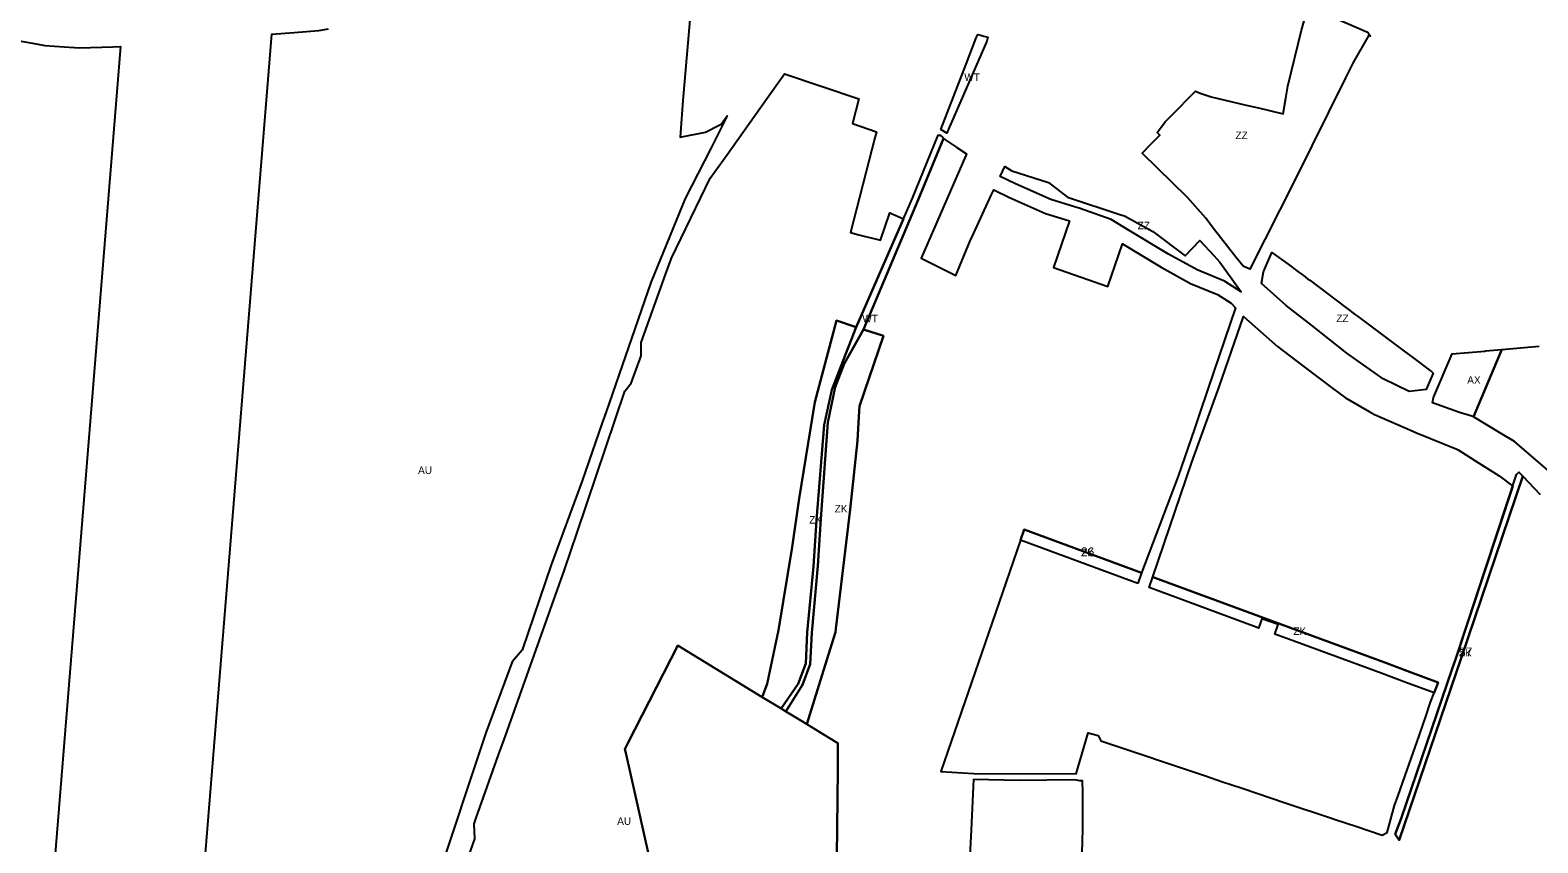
# Model space of a CAD drawing. Extents: x -545779 to -541342, y -1153413 to -1149956.
# Drawn here: x -544840 to -543834, y -1152010 to -1151467 of the extents above; entities that cross this region are included whole.
import ezdxf

# ---------------------------------------------------------------- set-up
doc = ezdxf.new("R2010")
doc.units = 0
for name, color, linetype in [('90640013', 7, 'Continuous'), ('90670013', 7, 'Continuous'), ('90710013', 7, 'Continuous'), ('90710023', 7, 'Continuous'), ('90730023', 7, 'Continuous'), ('90750013', 7, 'Continuous'), ('90760013', 7, 'Continuous'), ('90910012', 7, 'Continuous'), ('ID_navrh', 7, 'Continuous')]:
    doc.layers.add(name, color=color, linetype=linetype)

msp = doc.modelspace()

# ---------------------------------------------------------------- linework, layer by layer
at = {"layer": '90640013'}
for points in [[(-544232.03, -1151533.8), (-544215.08, -1151490.07), (-544208.32, -1151472.48), (-544207.36, -1151470.4), (-544204.65, -1151471.1), (-544203.29, -1151471.45), (-544200.59, -1151472.14), (-544201.35, -1151474.81), (-544226.79, -1151533.59), (-544228.04, -1151536.23)], [(-544338.6, -1151920.06), (-544327.25, -1151903.59), (-544322.08, -1151889.98), (-544321.13, -1151869.42), (-544316.9, -1151825.34), (-544314.86, -1151794.47), (-544309.78, -1151730.92), (-544304.78, -1151707.55), (-544298.72, -1151691.91), (-544288.37, -1151665.55), (-544256.81, -1151593.28), (-544250.8, -1151579.54), (-544233.62, -1151537.42), (-544232.47, -1151537.6), (-544230.64, -1151539.08), (-544230.06, -1151539.72), (-544247.16, -1151580.61), (-544283.6, -1151667.09), (-544296.39, -1151690.01), (-544302.4, -1151705.73), (-544307.28, -1151729.26), (-544312.02, -1151793.5), (-544313.95, -1151824.81), (-544318.14, -1151869.59), (-544319.12, -1151890.49), (-544324.34, -1151904.33), (-544335.32, -1151922.05)]]:
    msp.add_lwpolyline(points, close=True, dxfattribs=at)
at = {"layer": '90670013'}
msp.add_lwpolyline([(-543982.6, -1151453.35), (-543947.72, -1151468.6), (-543946.8, -1151469.22), (-543945.23, -1151471.42), (-543946.34, -1151470.89), (-543956.79, -1151488.97), (-543961.96, -1151499.28), (-543995.62, -1151567.47), (-544025.68, -1151626.95), (-544030.21, -1151624.9), (-544035.12, -1151618.93), (-544050.91, -1151598.59), (-544055.2, -1151593.01), (-544067.38, -1151579.03), (-544097.69, -1151549.46), (-544091.86, -1151543.49), (-544085.85, -1151537.43), (-544087.53, -1151535.79), (-544085.47, -1151532.93), (-544082.3, -1151528.55), (-544078.49, -1151524.76), (-544062.12, -1151508.24), (-544058.828, -1151509.401), (-544054.195, -1151511.034), (-544051.57, -1151511.96), (-544028.31, -1151517.41), (-544020.04, -1151519.34), (-544003.49, -1151523.2), (-544001.76, -1151512.89), (-544000.5, -1151504.81), (-543991.36, -1151467.47), (-543989.48, -1151461.15)], dxfattribs=at)
for points in [[(-544118.3, -1151593.88), (-544139.74, -1151586.23), (-544142.74, -1151585.3), (-544158.48, -1151580.44), (-544182.04, -1151569.98), (-544192.36, -1151565.06), (-544189.294, -1151558.541), (-544184.53, -1151561.26), (-544160.19, -1151569.12), (-544147.45, -1151578.92), (-544111.73, -1151590.65), (-544109.43, -1151591.41), (-544090.42, -1151601.91), (-544068.93, -1151618.03), (-544059.11, -1151607.82), (-544049.77, -1151617.91), (-544045.76, -1151622.18), (-544037.81, -1151633.31), (-544031.62, -1151641.99), (-544042.66, -1151635.02), (-544060.91, -1151627.39), (-544080.04, -1151616.83), (-544107.46, -1151600.39)], [(-543961.06, -1151683.01), (-543984.54, -1151664.4), (-544001.52, -1151651.15), (-544018.07, -1151636.61), (-544016.54, -1151628.79), (-544011.13, -1151615.89), (-544000.16, -1151623.63), (-543993.65, -1151628.41), (-543989.98, -1151631.22), (-543987.19, -1151633.32), (-543985.803, -1151634.36), (-543955.209, -1151657.314), (-543953.858, -1151658.328), (-543923.722, -1151680.938), (-543917.051, -1151685.943), (-543905.289, -1151694.767), (-543904.569, -1151695.308), (-543904.391, -1151695.441), (-543903.789, -1151695.893), (-543903.34, -1151696.23), (-543908.17, -1151707.27), (-543919.38, -1151708.54), (-543936.67, -1151700.16)]]:
    msp.add_lwpolyline(points, close=True, dxfattribs=at)
at = {"layer": '90710013'}
for points in [[(-544326.52, -1151780.05), (-544316.07, -1151715.64), (-544301.51, -1151661.3), (-544288.37, -1151665.55), (-544298.72, -1151691.91), (-544304.78, -1151707.55), (-544309.78, -1151730.92), (-544314.86, -1151794.47), (-544316.9, -1151825.34), (-544321.13, -1151869.42), (-544322.08, -1151889.98), (-544327.25, -1151903.59), (-544338.6, -1151920.06), (-544351.13, -1151912.42), (-544347.9, -1151903.54), (-544340.28, -1151867.89), (-544331.12, -1151812.43)], [(-544325.42, -1151928.09), (-544335.32, -1151922.05), (-544324.34, -1151904.33), (-544319.12, -1151890.49), (-544318.14, -1151869.59), (-544313.95, -1151824.81), (-544312.02, -1151793.5), (-544307.28, -1151729.26), (-544302.4, -1151705.73), (-544296.39, -1151690.01), (-544283.6, -1151667.09), (-544270.24, -1151671.42), (-544286.32, -1151718.42), (-544286.67, -1151725.2), (-544287.51, -1151741.53), (-544292.37, -1151787.39), (-544301.96, -1151866.85), (-544302.25, -1151869.25), (-544309.03, -1151891.14), (-544321.27, -1151930.63)], [(-543921.716, -1151902.65), (-543938.126, -1151896.589), (-543968.413, -1151885.402), (-543996.91, -1151874.876), (-544008.987, -1151870.416), (-544006.81, -1151863.97), (-544017.74, -1151860.181), (-544019.86, -1151866.399), (-544021.489, -1151865.798), (-544093.021, -1151839.376), (-544090.59, -1151832.3), (-544089.09, -1151832.83), (-544019.06, -1151858.7), (-543994.46, -1151867.78), (-543965.95, -1151878.31), (-543935.7, -1151889.49), (-543919.25, -1151895.56), (-543900.09, -1151902.64), (-543902.735, -1151909.661)]]:
    msp.add_lwpolyline(points, close=True, dxfattribs=at)
at = {"layer": '90710023'}
for points in [[(-543924.69, -1151993.54), (-543890.65, -1151893.58), (-543890.642, -1151893.555), (-543888.382, -1151886.723), (-543847.78, -1151763.96), (-543846.21, -1151762.33), (-543843.58, -1151765.07), (-543884.82, -1151886.48), (-543926.06, -1152007.84), (-543928.86, -1152003.9)], [(-544100.474, -1151836.623), (-544178.838, -1151807.679), (-544176.395, -1151800.585), (-544098.053, -1151829.541), (-544098.06, -1151829.56)]]:
    msp.add_lwpolyline(points, close=True, dxfattribs=at)
at = {"layer": '90730023'}
msp.add_lwpolyline([(-544335.32, -1151922.05), (-544325.42, -1151928.09), (-544321.27, -1151930.63), (-544306.99, -1151939.34), (-544300.59, -1151943.25), (-544300.75, -1151957.52), (-544300.79, -1151961.28), (-544302.75, -1152132.72), (-544304.26, -1152265.56), (-544304.43, -1152280.58), (-544367.57, -1152282.1), (-544370.25, -1152270.16), (-544401.66, -1152130.3), (-544421.06, -1152043.91), (-544421.06, -1152043.91), (-544433.09, -1151990.35), (-544442.21, -1151949.72), (-544442.79, -1151947.17), (-544440.77, -1151943.22), (-544407.5, -1151878.02), (-544351.13, -1151912.42), (-544338.6, -1151920.06)], close=True, dxfattribs=at)
at = {"layer": '90750013'}
for points in [[(-544398.431, -1151447.726), (-544404.191, -1151514.379), (-544405.968, -1151538.776), (-544388.93, -1151535.59), (-544379.85, -1151530.83), (-544378.59, -1151530.19), (-544374.44, -1151524.6), (-544385.47, -1151546.37), (-544402.51, -1151579.84), (-544425.47, -1151635.75), (-544455.29, -1151722.05), (-544457.88, -1151729.54), (-544471.2, -1151768.07), (-544492.05, -1151824.34), (-544511.33, -1151881.16), (-544517.9, -1151888.93), (-544535.68, -1151936.25), (-544569.04, -1152036.59)], [(-544863.56, -1151471.74), (-544835.58, -1151476.61), (-544829.76, -1151477.63), (-544817.04, -1151478.48), (-544806.75, -1151479.17), (-544784.41, -1151478.6), (-544779.283, -1151478.465), (-544841.973, -1152250.685)], [(-544742.287, -1152258.607), (-544678.286, -1151470.229), (-544663.43, -1151469.03), (-544646.97, -1151467.7), (-544640.54, -1151466.58)], [(-544549.76, -1152026.71), (-544543.02, -1152007.12), (-544543.4, -1151997.05), (-544541.95, -1151992.96), (-544525.9, -1151947.83), (-544523.61, -1151941.41), (-544496.26, -1151864.52), (-544483.08, -1151827.46), (-544474.71, -1151802.71), (-544474.71, -1151802.71), (-544442.81, -1151708.38), (-544438.68, -1151702.96), (-544432.02, -1151684.69), (-544431.97, -1151675.83), (-544415.57, -1151630.49), (-544411.63, -1151619.63), (-544385.88, -1151566.12), (-544374.27, -1151550.18), (-544348.98, -1151514.49), (-544336.264, -1151496.546), (-544286.643, -1151513.325), (-544290.981, -1151529.804), (-544274.838, -1151535.263), (-544275.88, -1151539.22), (-544292.132, -1151602.506), (-544286.65, -1151603.93), (-544272.13, -1151607.7), (-544265.97, -1151589.28), (-544256.81, -1151593.28), (-544288.37, -1151665.55), (-544301.51, -1151661.3), (-544316.07, -1151715.64), (-544326.52, -1151780.05), (-544331.12, -1151812.43), (-544340.28, -1151867.89), (-544347.9, -1151903.54), (-544351.13, -1151912.42), (-544407.5, -1151878.02), (-544440.77, -1151943.22), (-544442.79, -1151947.17), (-544442.21, -1151949.72), (-544433.09, -1151990.35), (-544421.06, -1152043.91)], [(-544302.75, -1152132.72), (-544300.79, -1151961.28), (-544300.75, -1151957.52), (-544300.59, -1151943.25), (-544306.99, -1151939.34), (-544321.27, -1151930.63), (-544309.03, -1151891.14), (-544302.25, -1151869.25), (-544301.96, -1151866.85), (-544292.37, -1151787.39), (-544287.51, -1151741.53), (-544286.67, -1151725.2), (-544286.32, -1151718.42), (-544270.24, -1151671.42), (-544283.6, -1151667.09), (-544247.16, -1151580.61), (-544230.06, -1151539.72), (-544229.19, -1151540.31), (-544221.23, -1151545.74), (-544214.8, -1151550.04), (-544215.31, -1151551.2), (-544245, -1151619.57), (-544221.98, -1151631.1), (-544212.31, -1151607.99), (-544210.19, -1151603.35), (-544198.06, -1151577.18), (-544196.616, -1151574.109), (-544186.221, -1151579.065), (-544161.996, -1151589.82), (-544145.997, -1151594.76), (-544156.671, -1151625.758), (-544120.556, -1151638.42), (-544110.788, -1151610.054), (-544085.029, -1151625.498), (-544065.268, -1151636.407), (-544047.29, -1151643.923), (-544038.099, -1151649.726), (-544035.294, -1151652.8), (-544049.74, -1151695.3), (-544058.9, -1151722.15), (-544062.77, -1151733.47), (-544073.55, -1151765.03), (-544098.053, -1151829.541), (-544176.395, -1151800.585), (-544178.838, -1151807.679), (-544190.89, -1151842.68), (-544232.03, -1151962.15), (-544209.95, -1151963.48), (-544141.65, -1151963.58), (-544133.597, -1151936.229), (-544126.97, -1151938.18), (-544125.19, -1151941.77), (-544055.43, -1151965.13), (-544044.66, -1151968.73), (-544030.88, -1151973.35), (-544002.09, -1151982.98), (-543971.18, -1151993.33), (-543968.05, -1151994.38), (-543955.12, -1151998.7), (-543937.55, -1152004.59), (-543934.17, -1152002.91), (-543929.23, -1151984.87), (-543926.75, -1151978.09), (-543923.89, -1151969.9), (-543922.08, -1151964.71), (-543912.85, -1151938.25), (-543909.92, -1151929.94), (-543908.53, -1151926), (-543905.1, -1151915.94), (-543902.735, -1151909.661), (-543900.09, -1151902.64), (-543919.25, -1151895.56), (-543935.7, -1151889.49), (-543965.95, -1151878.31), (-543994.46, -1151867.78), (-544019.06, -1151858.7), (-544089.09, -1151832.83), (-544090.59, -1151832.3), (-544064.41, -1151755.76), (-544046.26, -1151705.45), (-544029.924, -1151658.578), (-544007.329, -1151678.515), (-543989.51, -1151692.188), (-543970.28, -1151706.502), (-543961.808, -1151712.806), (-543946.032, -1151721.939), (-543942.663, -1151723.881), (-543917.013, -1151735.088), (-543914.543, -1151736.16), (-543887.656, -1151747.084), (-543886.723, -1151747.463), (-543873.185, -1151756.069), (-543859.362, -1151764.855), (-543850.356, -1151771.75), (-543888.382, -1151886.723), (-543890.642, -1151893.555), (-543890.65, -1151893.58), (-543924.69, -1151993.54), (-543928.86, -1152003.9), (-543926.06, -1152007.84), (-543884.82, -1151886.48), (-543843.58, -1151765.07), (-543831.95, -1151777.22)], [(-543818.82, -1151767.88), (-543849.25, -1151741.95), (-543857.35, -1151737.01), (-543876.44, -1151725.37), (-543857.563, -1151680.522), (-543832.723, -1151678.258)]]:
    msp.add_lwpolyline(points, dxfattribs=at)
msp.add_lwpolyline([(-544216.21, -1152087.96), (-544217.12, -1152120.01), (-544189.83, -1152119.54), (-544157.13, -1152118.8), (-544145.23, -1152094.69), (-544137.48, -1152075.92), (-544135.77, -1152066.84), (-544137.89, -1152024.68), (-544137.24, -1152000.5), (-544137.3, -1151975.86), (-544137.32, -1151968.36), (-544139.1, -1151968.37), (-544142.54, -1151967.58), (-544179.69, -1151968.08), (-544210.18, -1151967.43), (-544211.7, -1152001)], close=True, dxfattribs=at)
at = {"layer": '90760013'}
msp.add_lwpolyline([(-543903.08, -1151712.52), (-543890.633, -1151683.536), (-543868.931, -1151681.558), (-543868.517, -1151681.52), (-543857.563, -1151680.522), (-543876.44, -1151725.37), (-543877.54, -1151725.05), (-543885.87, -1151722.63), (-543903.8, -1151716.11)], close=True, dxfattribs=at)
at = {"layer": '90910012'}
msp.add_lwpolyline([(-543857.563, -1151680.522), (-543876.44, -1151725.37)], dxfattribs=at)

# ---------------------------------------------------------------- texts
at = {"layer": '90640013'}
for p in [(-544216.31, -1151501.309), (-544284.33, -1151662.348)]:
    msp.add_text('WT', height=5, rotation=0, dxfattribs=at).set_placement(p)
at = {"layer": '90670013'}
for rotation, p in [(360, (-544035.341, -1151540.15)), (0, (-544100.532, -1151600.265)), (360, (-543968.009, -1151662.215))]:
    msp.add_text('ZZ', height=5, rotation=rotation, dxfattribs=at).set_placement(p)
at = {"layer": '90710013'}
for rotation, p in [(360, (-544302.78, -1151789.262)), (0, (-544319.75, -1151796.681)), (360, (-543996.627, -1151870.981))]:
    msp.add_text('ZK', height=5, rotation=rotation, dxfattribs=at).set_placement(p)
at = {"layer": '90710023'}
for p in [(-544138.451, -1151818.604), (-543886.22, -1151885.393)]:
    msp.add_text('ZK', height=5, rotation=360, dxfattribs=at).set_placement(p)
at = {"layer": '90750013'}
for rotation, p in [(360, (-544580.772, -1151763.587)), (0, (-544447.9, -1151997.726))]:
    msp.add_text('AU', height=5, rotation=rotation, dxfattribs=at).set_placement(p)
at = {"layer": '90760013'}
msp.add_text('AX', height=5, rotation=0, dxfattribs=at).set_placement((-543880.682, -1151703.383))
at = {"layer": 'ID_navrh'}
for s, rotation, p in [('26', 360, (-544138.451, -1151818.604)), ('57', 0, (-543886.22, -1151885.393))]:
    msp.add_text(s, height=6, rotation=rotation, dxfattribs=at).set_placement(p)

doc.saveas('drawing.dxf')
